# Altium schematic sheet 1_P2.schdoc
size 426 x 302 mm
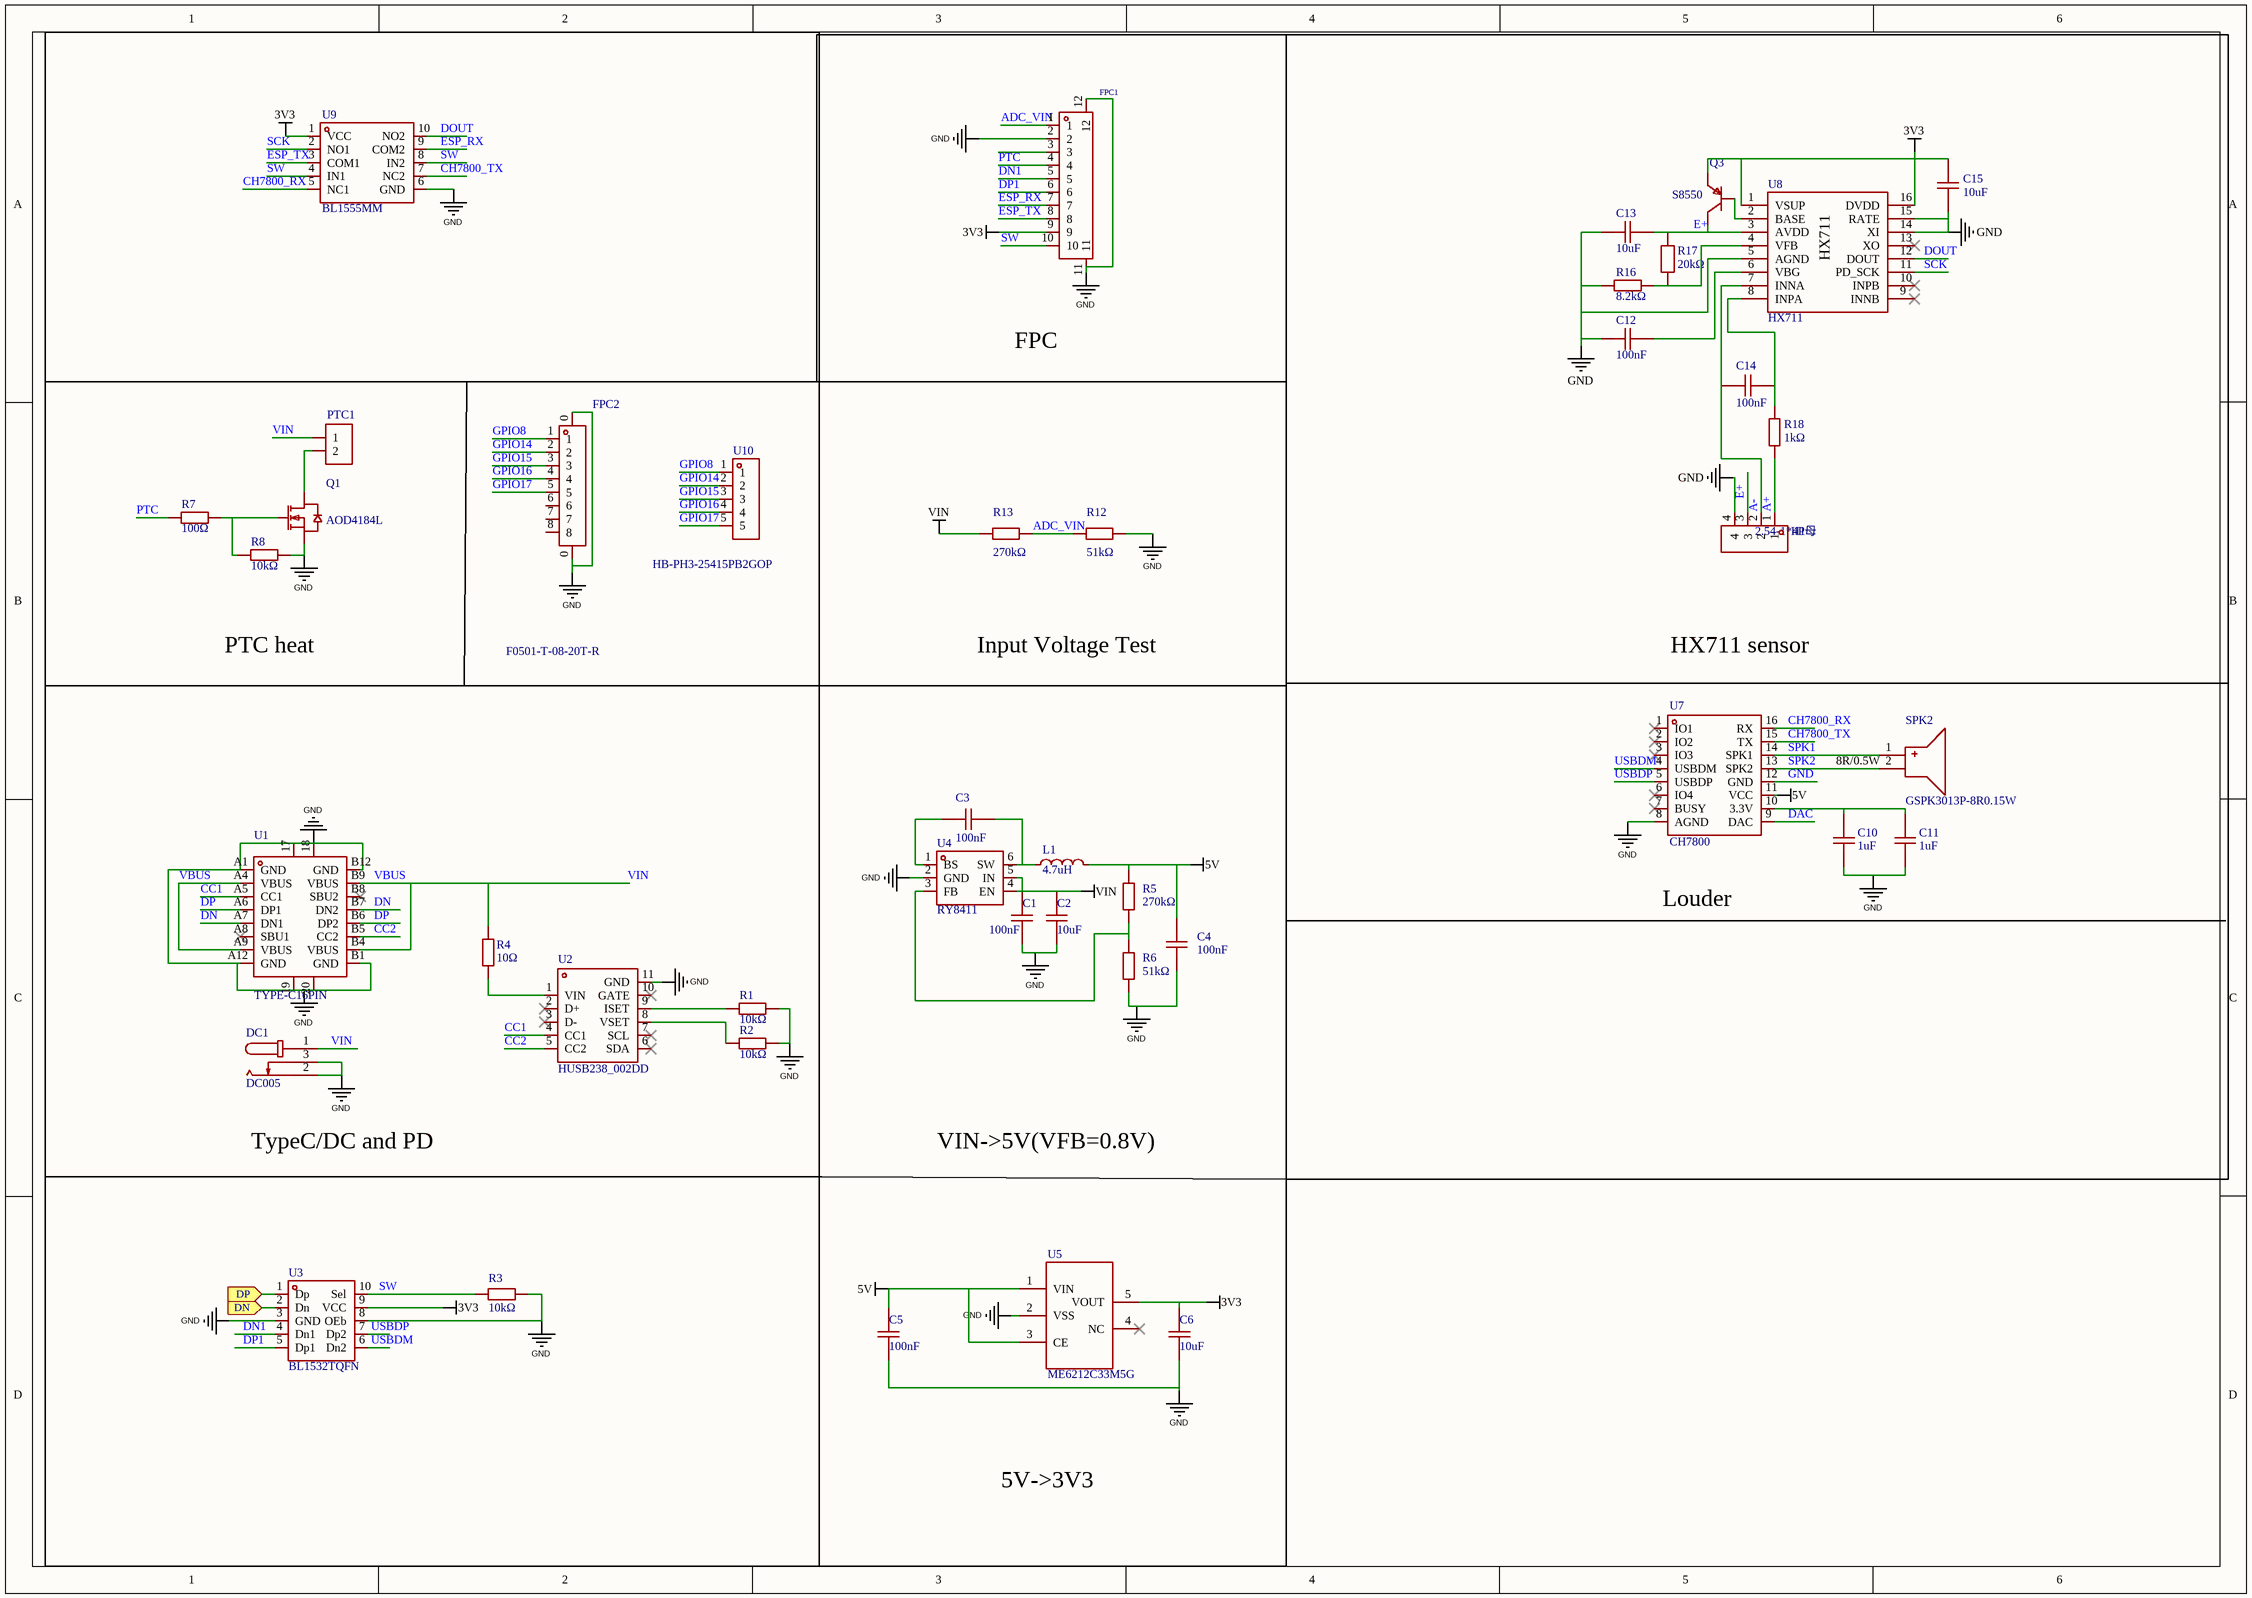
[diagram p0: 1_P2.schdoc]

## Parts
C1  100nF  [C0603]
C2  10uF  [C0603]
C3  100nF  [C0603]
C4  100nF  [C0603]
C5  100nF  [C0603]
C6  10uF  [C0603]
C10  1uF  [C0603]
C11  1uF  [C0603]
C12  100nF  [C0603]
C13  10uF  [C0603]
C14  100nF  [C0603]
C15  10uF  [C0603]
DC1  DC005  [DC-IN-TH_DC005]
FPC1  F0501-T-10-20T-R  [FPC-SMD_F0501-T-10-20T-R]  (value not drawn)
FPC2  F0501-T-08-20T-R  [FPC-SMD_8P-P0.50_L4.4-W9.6]
H1  2.54-1*4P母  [hdr-th_4p-p2.54-v-f]
L1  4.7uH  [IND-SMD_L3.5-W3.0]
PTC1  (no value)  [HDR-TH_2P-P2.54-V-F]
Q1  AOD4184L  [TO-252-2_L6.6-W6.1-P4.57-LS9.9-TL-CW]
Q3  S8550  [SOT-23-3_L2.9-W1.3-P1.90-LS2.4-BR]
R1  10kΩ  [R0603]
R2  10kΩ  [R0603]
R3  10kΩ  [R0603]
R4  10Ω  [R0603]
R5  270kΩ  [R0603]
R6  51kΩ  [R0603]
R7  100Ω  [R0603]
R8  10kΩ  [R0603]
R12  51kΩ  [R0603]
R13  270kΩ  [R0603]
R16  8.2kΩ  [R0603]
R17  20kΩ  [R0603]
R18  1kΩ  [R0603]
SPK2  GSPK3013P-8R0.15W  [SPK-TH_BD30.0-P15.00-D0.8-L-RD]
U1  TYPE-C16PIN  [USB-C-SMD_TYPE-C16PIN]
U2  HUSB238_002DD  [DFN-10_L3.0-W3.0-P0.50-BL-EP2.5]
U3  BL1532TQFN  [QFN-10_L1.4-W1.8-P0.40-BL]
U4  RY8411  [SOT-23-6_L2.9-W1.6-P0.95-LS2.8-TL]
U5  ME6212C33M5G  [SOT-23-5_L3.0-W1.7-P0.95-LS2.8-BL]
U7  CH7800  [SOP-16_L9.9-W3.9-P1.27-LS6.0-BL]
U8  HX711  [SOP-16_L10.0-W3.9-P1.27-LS6.0-BL]
U9  BL1555MM  [MSOP-10_L3.0-W3.0-P0.50-LS5.0-BL]
U10  HB-PH3-25415PB2GOP  [HDR-TH_5P-P2.54-V-M]

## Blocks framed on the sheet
FPC: FPC1
HX711 sensor: C12-C15 H1 Q3 R16-R18 U8
PTC heat: FPC2 PTC1 Q1 R7 R8 U10
Input Voltage Test: R12 R13
TypeC/DC and PD: DC1 R1-R4 U1-U3
Louder: C10 C11 SPK2 U7

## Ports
DN (in), DP (in)

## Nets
3V3: C6.1 C15.1 FPC1.9 Q3.2(E) U3.9(VCC) U5.5(VOUT) U8.1(VSUP) U8.16(DVDD) U9.1(VCC)
5V: C4.1 C5.1 L1.2 R5.2 U5.1(VIN) U5.3(CE) U7.11(VCC)
GND: C1.2 C2.2 C4.2 C5.2 C6.2 C10.1 C11.1 C12.2 C13.2 C15.2 DC1.2 DC1.3 FPC1.2 FPC1.11 FPC1.12 FPC2.0 H1.4 Q1.3(S) R1.2 R2.2 R3.1 R6.1 R8.2 R12.2 R16.1 U1.17 U1.18 U1.19 U1.20 U1.A1(GND) U1.A12(GND) U1.B1(GND) U1.B12(GND) U2.11(GND) U3.3(GND) U3.8(OEb) U4.2(GND) U5.2(VSS) U7.8(AGND) U7.12(GND) U8.5(AGND) U8.14(XI) U8.15(RATE) U9.6(GND)
VBUS: C1.1 C2.1 DC1.1 PTC1.1 R4.2 R13.1 U1.A4(VBUS) U1.A9(VBUS) U1.B4(VBUS) U1.B9(VBUS) U4.4(EN) U4.5(IN)  [also labelled VIN]
A+: H1.1 R18.1
A-: C14.2 H1.2 U8.7(INNA)
ADC_VIN: FPC1.1 R12.1 R13.2
CC1: U1.A5(CC1) U2.4(CC1)
CC2: U1.B5(CC2) U2.5(CC2)
CH7800_RX: U7.16(RX) U9.5(NC1)
CH7800_TX: U7.15(TX) U9.7(NC2)
DAC: U7.9(DAC)
DN: U3.2(Dn) ; port DN
DN: U1.A7(DN1) U1.B7(DN2)  [a separate net that carries the same name]
DN1: FPC1.5 U3.4(Dn1)
DOUT: U8.12(DOUT) U9.10(NO2)
DP: U3.1(Dp) ; port DP
DP: U1.A6(DP1) U1.B6(DP2)  [a separate net that carries the same name]
DP1: FPC1.6 U3.5(Dp1)
E+: C13.1 H1.3 Q3.3(C) R17.2 U8.3(AVDD)
ESP_RX: FPC1.7 U9.9(COM2)
ESP_TX: FPC1.8 U9.3(COM1)
GPIO8: FPC2.1 U10.1
GPIO14: FPC2.2 U10.2
GPIO15: FPC2.3 U10.3
GPIO16: FPC2.4 U10.4
GPIO17: FPC2.5 U10.5
PTC: FPC1.4 R7.1
SCK: U8.11(PD_SCK) U9.2(NO1)
SPK1: SPK2.1(+) U7.14(SPK1)
SPK2: SPK2.2(-) U7.13(SPK2)
SW: FPC1.10 R3.2 U3.10(Sel) U9.4(IN1) U9.8(IN2)
USBDM: U3.6(Dn2) U7.4(USBDM)
USBDP: U3.7(Dp2) U7.5(USBDP)
NetC3_1: C3.1 U4.1(BS)
NetC3_2: C3.2 L1.1 U4.6(SW)
NetC10_2: C10.2 C11.2 U7.10(3.3V)
NetC12_1: C12.1 U8.6(VBG)
NetC14_1: C14.1 R18.2 U8.8(INPA)
NetPTC1_2: PTC1.2 Q1.2(D)
NetQ1_1: Q1.1(G) R7.2 R8.1
NetQ3_1: Q3.1(B) U8.2(BASE)
NetR1_1: R1.1 U2.9(ISET)
NetR2_1: R2.1 U2.8(VSET)
NetR4_1: R4.1 U2.1(VIN)
NetR5_1: R5.1 R6.2 U4.3(FB)
NetR16_2: R16.2 R17.1 U8.4(VFB)

Not connected (* = marked no-connect by the designer): FPC1 3; FPC2 6 7 8; U1 A8(SBU1)* B8(SBU2)*; U2 2(D+)* 3(D-)* 6(SDA)* 7(SCL)* 10(GATE)*; U5 4(NC)*; U7 1(IO1)* 2(IO2)* 3(IO3)* 6(IO4)* 7(BUSY)*; U8 9(INNB)* 10(INPB)* 13(XO)*

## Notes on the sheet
- (near SPK2) 8R/0.5W
- VIN->5V(VFB=0.8V)
- 5V->3V3

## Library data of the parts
C1 C3-C5 = CGA0603X7R104K500JT: Manufacturer: HRE(芯声); Symbol: CapAcitance; Add into BOM: yes; Tolerance: ±10%; Voltage Rated: 50V; Temperature Coefficient: X7R
C2 C6 = CL10A106KP8NNNC: Manufacturer: SAMSUNG(三星); Symbol: CapAcitance; Add into BOM: yes; Tolerance: ±10%; Voltage Rated: 10V; Temperature Coefficient: X5R
C10 C11 = CL10A105KA8NNNC: Manufacturer: SAMSUNG(三星); Symbol: CapAcitance; Add into BOM: yes; Tolerance: ±10%; Voltage Rated: 25V; Temperature Coefficient: X5R
C12 = CGA0603X7R104K500JT: Manufacturer: HRE(芯声); Symbol: 1uF; Add into BOM: yes; Tolerance: ±10%; Voltage Rated: 50V; Temperature Coefficient: X7R
C13 C15 = CL10A106KP8NNNC: Manufacturer: SAMSUNG(三星); Symbol: 1uF; Add into BOM: yes; Tolerance: ±10%; Voltage Rated: 10V; Temperature Coefficient: X5R
C14 = CC0603KRX7R9BB104: Manufacturer: YAGEO(国巨); Add into BOM: yes; Tolerance: ±10%; Voltage Rated: 50V; Temperature Coefficient: X7R
DC1 = DC005: Manufacturer: SHOU HAN(首韩); Symbol: DC005_C431533; Add into BOM: yes; Connector Type: DC电源插座; Inside Contact Diameter: 2mm; Outside Contact Diameter: 6.3mm; Current Rating (Max): 500mA; Voltage Rating (Max): 30V
FPC1 = F0501-T-10-20T-R: Manufacturer: XFCN(兴飞); Add into BOM: yes; Pitch: 0.5mm; Number of Contacts: 10P; Locking Feature: 抽屉式
FPC2 = F0501-T-08-20T-R: Manufacturer: XFCN(兴飞); Add into BOM: yes; Locking Feature: 抽屉式; Number of Contacts: 8P; Pitch: 0.5mm
H1 = 2.54-1*4P母: Manufacturer: BOOMELE(博穆精密); Add into BOM: yes; Holes Structure: 1x4P; Pitch: 2.54mm; Circular Hole / Square Hole: 方孔; Number of Holes: 4P; Current Rating (Max): 3A; Holes Direction: 顶部; Check: false
L1 = CD32-4R7M 4.7UH: Manufacturer: DMBJ(振宝佳); Add into BOM: yes; Tolerance: ±20%; Rated Current: 1.5A; DC Resistance (DCR): 137mΩ
PTC1 = HDR-F_2.54_1x2P: Manufacturer: BOOMELE(博穆精密); Manufacturer Part: 2.54-1*2P母; Symbol: Header-Female-2.54_1x2; Convert to PCB: yes
Q1 = AOD4184L: Manufacturer: AOS; Add into BOM: yes; Type: 1个N沟道; Drain Source Voltage (Vdss): 40V; Continuous Drain Current (Id): 50A; Drain Source On Resistance (RDS(on)@Vgs,Id): 8mΩ@10V,20A; Power Dissipation (Pd): 50W; Gate Threshold Voltage (Vgs(th)@Id): 3V@250uA
Q3 = S8550_C20069126: Manufacturer: 宏迦橙; Add into BOM: yes; Transistor Type: PNP; Collector Current (Ic): 500mA; Collector-Emitter Breakdown Voltage (Vceo): 25V; Power Dissipation (Pd): 300mW; DC Current Gain (hFE@Ic,Vce): 120@500mA,1.0V; Transition Frequency (fT): 150MHz; Collector Cut-Off Current (Icbo): 100nA; Collector-Emitter Saturation Voltage (VCE(sat)@Ic,Ib): 500mV@1.0A,50mA
R1-R3 R8 = 0603WAF1002T5E: Manufacturer: UNI-ROYAL(厚声); Symbol: 电阻; Add into BOM: yes; Tolerance: ±1%; Power(Watts): 100mW; Overload Voltage (Max): 75V; Temperature Coefficient: ±100ppm/℃
R4 = 0603WAF100JT5E: Manufacturer: UNI-ROYAL(厚声); Symbol: 电阻; Add into BOM: yes; Tolerance: ±1%; Power(Watts): 100mW; Overload Voltage (Max): 75V; Temperature Coefficient: ±400ppm/℃
R5 = FRC0603F2703TS: Manufacturer: FOJAN(富捷); Symbol: 电阻; Add into BOM: yes; Tolerance: ±1%; Power(Watts): 100mW; Overload Voltage (Max): 75V; Temperature Coefficient: ±100ppm/℃
R6 R12 = 0603WAF5102T5E: Manufacturer: UNI-ROYAL(厚声); Symbol: 电阻; Add into BOM: yes; Tolerance: ±1%; Power(Watts): 100mW; Overload Voltage (Max): 75V; Temperature Coefficient: ±100ppm/℃
R7 = 0603WAF1000T5E: Manufacturer: UNI-ROYAL(厚声); Symbol: 电阻; Add into BOM: yes; Tolerance: ±1%; Power(Watts): 100mW; Overload Voltage (Max): 75V; Temperature Coefficient: ±200ppm/℃
R13 = 0603WAF2703T5E: Manufacturer: UNI-ROYAL(厚声); Symbol: 电阻; Add into BOM: yes; Tolerance: ±1%; Power(Watts): 100mW; Overload Voltage (Max): 75V; Temperature Coefficient: ±100ppm/℃
R16 = 0603WAF8201T5E: Manufacturer: UNI-ROYAL(厚声); Symbol: 8.2K; Add into BOM: yes; Tolerance: ±1%; Power(Watts): 100mW; Overload Voltage (Max): 75V; Temperature Coefficient: ±100ppm/℃
R17 = 0603WAF2002T5E: Manufacturer: UNI-ROYAL(厚声); Symbol: 20K; Add into BOM: yes; Tolerance: ±1%; Power(Watts): 100mW; Overload Voltage (Max): 75V; Temperature Coefficient: ±100ppm/℃
R18 = 0603WAF1001T5E: Manufacturer: UNI-ROYAL(厚声); Symbol: 1K; Add into BOM: yes; Tolerance: ±1%; Power(Watts): 100mW; Overload Voltage (Max): 75V; Temperature Coefficient: ±100ppm/℃
SPK2 = GSPK3013P-8R0.15W: Manufacturer: INGHAi(赢海); Add into BOM: yes
U1 = TYPE-C16PIN: Manufacturer: SHOU HAN(首韩); Symbol: TYPE-C16PIN母座 板上四脚三次MOLDING; Add into BOM: yes; Connector Type: Type-C; Gender: 母; Number of Contacts: 16P; Number of Ports: 1; Current Rating - Power (Max): 3A; Rated Voltage (Max): 30V; Connect-Disconnect Life: 1万次; Core Colour: 黑色
U2 = HUSB238_002DD: Manufacturer: Hynetek(慧能泰); Symbol: HUSB238-002D; Add into BOM: yes
U3 = BL1532TQFN: Manufacturer: BL(上海贝岭); Add into BOM: yes
U4 = RY8411_C2935411: Manufacturer: RYCHiP(蕊源); Add into BOM: yes
U5 = ME6212C33M5G: Manufacturer: MICRONE(南京微盟); Add into BOM: yes; Output Type: 固定; Maximum Input Voltage: 6V; Output Voltage: 3.3V; MAX Output Current: 350mA; Power Supply Rejection Ratio (PSRR): 65dB; Dropout Voltage: 260mV@(200mA); Output Polarity: 正极; Number of Outputs: 1
U7 = CH7800: Add into BOM: yes
U8 = HX711_C6705483: Manufacturer: AVIA(海芯科技); Add into BOM: yes; resolution: 24位; number of channels: 2; Supply Voltage: 2.7V~5.5V; differential input: 是
U9 = BL1555MM: Manufacturer: BL(上海贝岭); Add into BOM: yes
U10 = HB-PH3-25415PB2GOP: Manufacturer: HANBO(汉博); Add into BOM: yes; Pin Structure: 1x5P; Pitch: 2.54mm; Circluar Pins/Square Pins: 方针; Current Rating (Max): 3A; Voltage Rating (Max): 250V; Soldering Temperature(Max): 260℃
